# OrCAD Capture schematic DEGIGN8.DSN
size A; title: Smart RGB LED
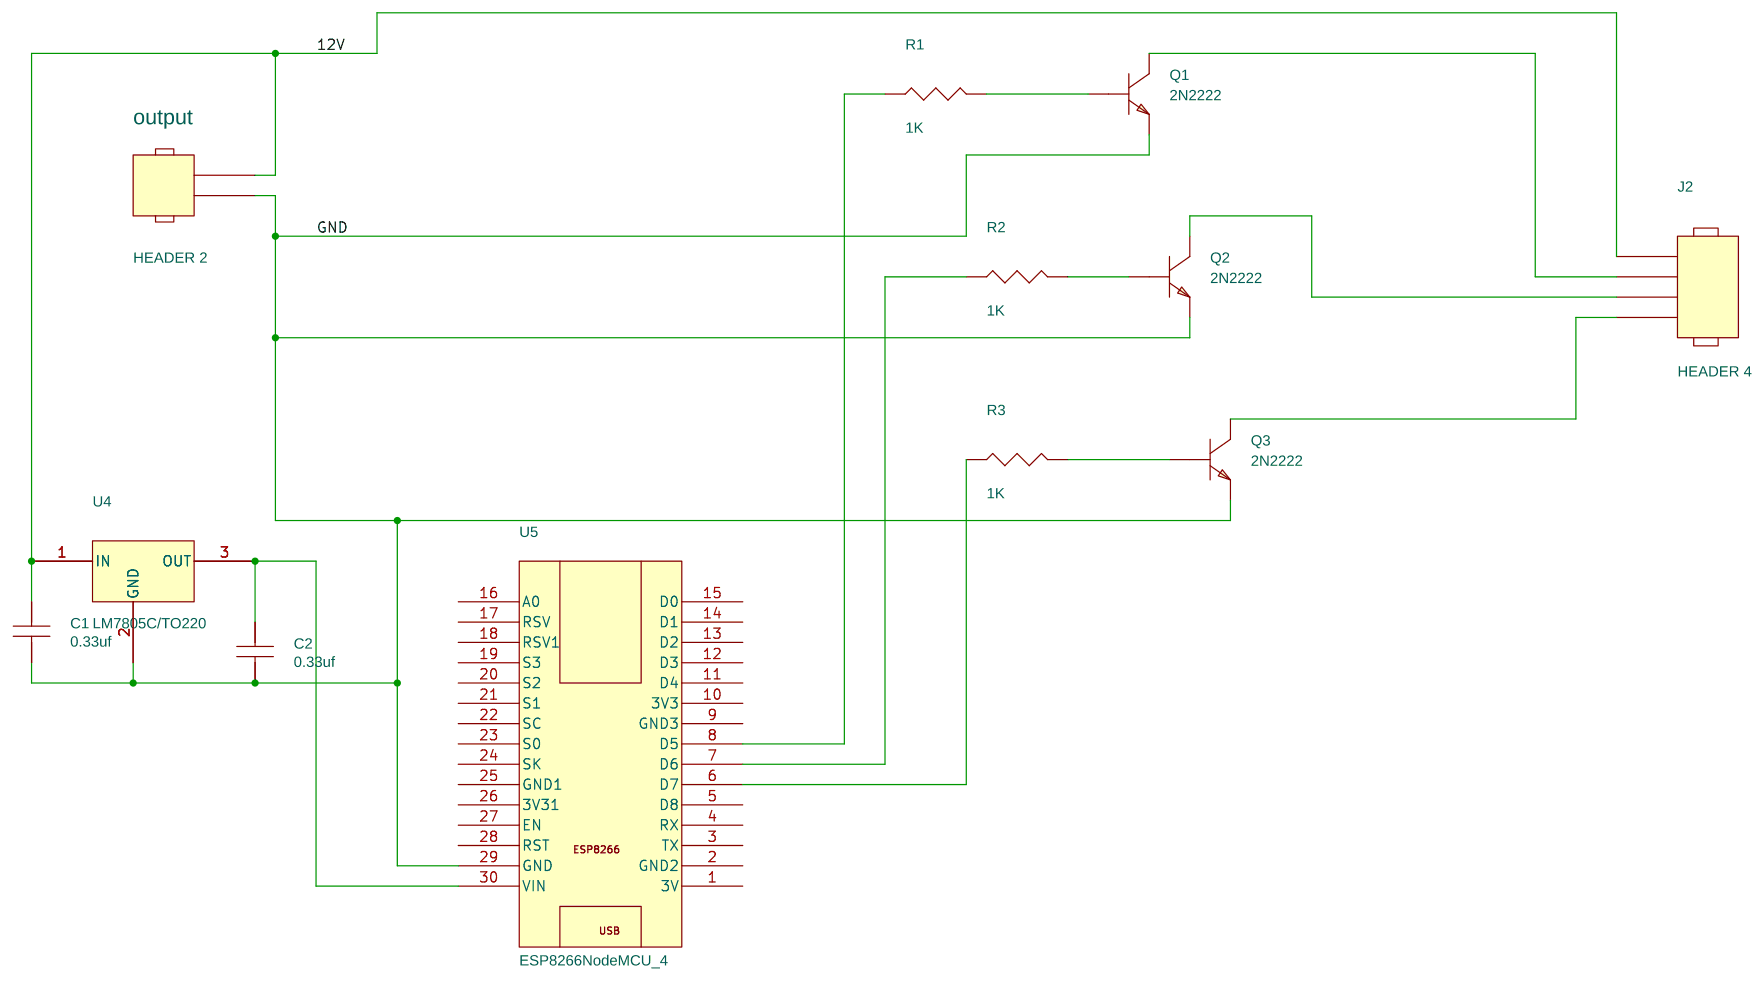
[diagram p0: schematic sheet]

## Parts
C1  0.33uf  [GU-CAPCYL100]
C2  0.33uf  [GU-CAPCYL100]
J2  HEADER 4  [GU-MOLEX4]
output  HEADER 2  [GU-TERMINAL2-200]
Q1  2N2222  [GU-TO92-100]
Q2  2N2222  [GU-TO92-100]
Q3  2N2222  [GU-TO92-100]
R1  1K  [GU-RC300]
R2  1K  [GU-RC300]
R3  1K  [GU-RC300]
U4  LM7805C/TO220  [GU-TO220AB]
U5  ESP8266NodeMCU_4

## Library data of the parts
C1 C2 = CAPACITOR_NON-POL
J2 = HEADER_4
output = HEADER_2
Q1-Q3 = 2N2222
R1-R3 = R
U4 = LM7805C_TO220_0
U5 = ESP8266NodeMCU_4

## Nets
12V: C1.1 J2.4 output.1 U4.1(IN)
GND: C1.2 C2.2 output.2 Q1.1(EMITTER) Q2.1(EMITTER) Q3.1(EMITTER) U4.2(GND) U5.29(GND)
N26259: Q2.2(BASE) R2.2
N26267: Q3.2(BASE) R3.2
N28423: C2.1 U4.3(OUT) U5.30(VIN)
N28430: R1.1 U5.8(D5)
N28437: R2.1 U5.7(D6)
N28467: R3.1 U5.6(D7)
N28563: J2.3 Q1.3(COLLECTOR)
N28577: J2.1 Q3.3(COLLECTOR)
N29703: J2.2 Q2.3(COLLECTOR)
N33667: Q1.2(BASE) R1.2

Not connected (* = marked no-connect by the designer): U5 1(3V) 2(GND2) 3(TX) 4(RX) 5(D8) 9(GND3) 10(3V3) 11(D4) 12(D3) 13(D2) 14(D1) 15(D0) 16(A0) 17(RSV) 18(RSV1) 19(S3) 20(S2) 21(S1) 22(SC) 23(S0) 24(SK) 25(GND1) 26(3V31) 27(EN) 28(RST)
